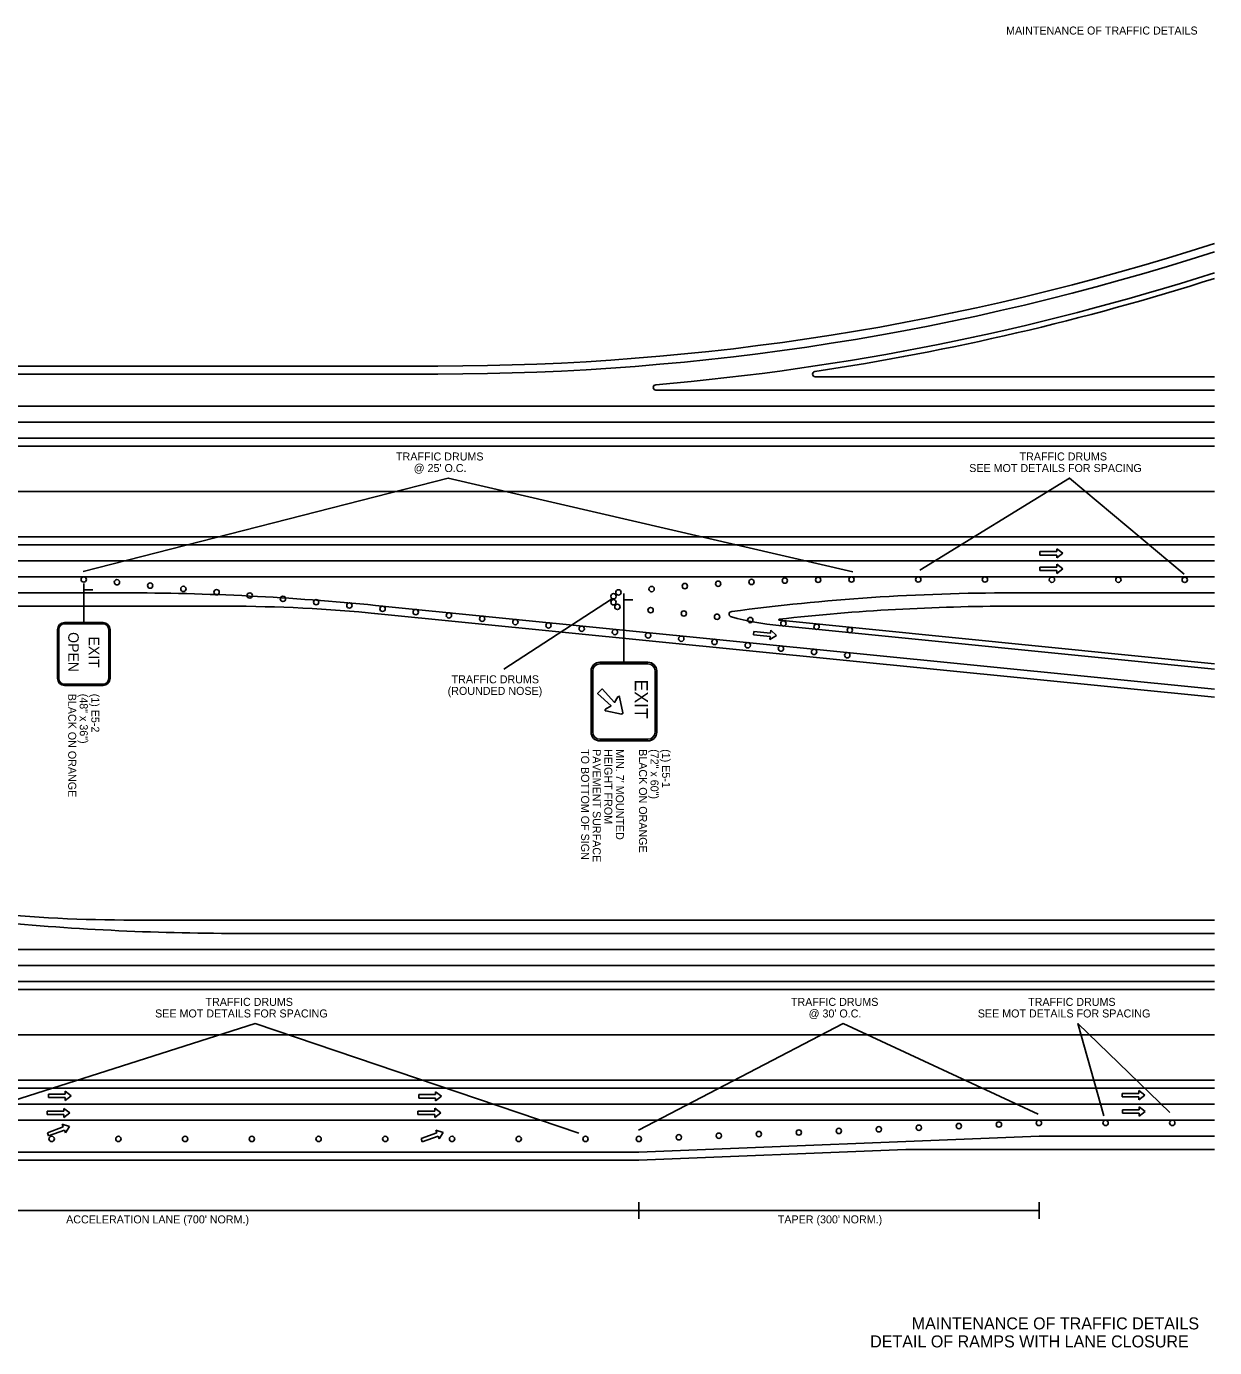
# Model space of a CAD drawing. Extents: x 1373848 to 1374003, y 380642 to 381248.
# Drawn here: x 1373914.2 to 1374003.2, y 380810.3 to 380909.4 of the extents above; entities that cross this region are included whole.
import ezdxf

# ---------------------------------------------------------------- set-up
doc = ezdxf.new("R2010")
doc.units = 0
for name, color, linetype in [('Default', 7, 'Continuous'), ('G-ANNO-TEXT', 7, 'Continuous'), ('R_Horz Alg', 7, 'Continuous'), ('R_MOT', 7, 'Continuous')]:
    doc.layers.add(name, color=color, linetype=linetype)

# ---------------------------------------------------------------- blocks, each defined once
blk = doc.blocks.new('SARROW')
at = {"layer": 'Default'}
for p, q in [((15.6, 3.2), (-13.8, 3.2)), ((-13.8, 3.2), (-13.8, -2.8)), ((15.6, 8.2), (15.6, 3.2)), ((15.6, 8.2), (26, 0.2)), ((26, 0.2), (15.6, -7.8)), ((15.6, -2.8), (-13.8, -2.8)), ((15.6, -2.8), (15.6, -7.8))]:
    blk.add_line(p, q, dxfattribs=at)

msp = doc.modelspace()

# ---------------------------------------------------------------- linework, layer by layer
at = {"layer": 'Default'}
for p, q in [((1373945.02, 380883.909), (1373891.355, 380883.909)), ((1373945.02, 380883.309), (1373891.355, 380883.309)), ((1373973.291, 380883.109), (1374003.214, 380883.109)), ((1373961.355, 380882.109), (1374003.214, 380882.109)), ((1373848.214, 380880.909), (1374003.214, 380880.909)), ((1373848.214, 380879.709), (1374003.214, 380879.709)), ((1373848.214, 380878.509), (1374003.214, 380878.509)), ((1373848.214, 380877.909), (1374003.214, 380877.909)), ((1373848.214, 380874.509), (1374003.214, 380874.509)), ((1373848.214, 380871.109), (1374003.214, 380871.109)), ((1373848.214, 380870.509), (1374003.214, 380870.509)), ((1373848.214, 380869.309), (1374003.214, 380869.309)), ((1373848.214, 380868.109), (1374003.214, 380868.109)), ((1373848.214, 380866.909), (1373921.443, 380866.909)), ((1373988.03, 380866.909), (1374003.214, 380866.909)), ((1373848.214, 380865.909), (1373929.25, 380865.909)), ((1374003.214, 380859.079), (1373940.282, 380865.37)), ((1374003.214, 380859.682), (1373940.342, 380865.967)), ((1374003.214, 380865.909), (1373988.03, 380865.909)), ((1374003.214, 380861.19), (1373970.562, 380864.453)), ((1374003.214, 380861.592), (1373970.602, 380864.851)), ((1374003.214, 380842.381), (1373922.177, 380842.381)), ((1374003.214, 380841.381), (1373929.984, 380841.381)), ((1374003.214, 380840.181), (1373848.214, 380840.181)), ((1374003.214, 380838.981), (1373848.214, 380838.981)), ((1374003.214, 380837.781), (1373848.214, 380837.781)), ((1374003.214, 380837.181), (1373848.214, 380837.181)), ((1374003.214, 380833.781), (1373848.214, 380833.781)), ((1374003.214, 380830.381), (1373848.214, 380830.381)), ((1374003.214, 380829.781), (1373848.214, 380829.781)), ((1374003.214, 380828.581), (1373848.214, 380828.581)), ((1374003.214, 380827.381), (1373848.214, 380827.381)), ((1373960.072, 380824.981), (1373990.072, 380826.181)), ((1373990.072, 380826.181), (1374003.214, 380826.181)), ((1373906.407, 380824.981), (1373960.072, 380824.981)), ((1373960.072, 380824.381), (1373980.072, 380825.181)), ((1373980.072, 380825.181), (1374003.214, 380825.181)), ((1373906.407, 380824.381), (1373960.072, 380824.381)), ((1373960.072, 380820.608), (1373890.072, 380820.608)), ((1373960.072, 380821.233), (1373960.072, 380819.983)), ((1373960.072, 380820.608), (1373990.072, 380820.608)), ((1373990.072, 380821.233), (1373990.072, 380819.983))]:
    msp.add_line(p, q, dxfattribs=at)
for centre, radius, start, end in [((1373945.02, 381072.559), 188.65, 270, 287.96736), ((1373945.02, 381072.559), 189.25, 270, 287.90846), ((1373945.02, 381072.559), 190.75, 274.90749, 287.76292), ((1373945.02, 381072.559), 191.15, 278.49632, 287.72452), ((1373973.291, 380883.309), 0.2, 98.49632, 270), ((1373961.355, 380882.309), 0.2, 94.90749, 270), ((1373921.443, 380676.909), 190, 84.29167, 90), ((1373988.03, 380708.709), 158.2, 90, 97.62815), ((1373929.25, 380752.831), 113.078, 84.29167, 90), ((1373967.03, 380865.309), 0.2, 90, 264.29167), ((1373988.03, 380708.709), 157.2, 90, 96.36869), ((1373972.726, 380886.096), 21.75, 254.76438, 264.29167), ((1373970.604, 380864.896), 0.0444, 104.39417, 268.34322), ((1373922.177, 380955.458), 113.078, 264.29167, 270), ((1373929.984, 381031.381), 190, 264.29167, 270)]:
    msp.add_arc(centre, radius, start, end, dxfattribs=at)
at = {"layer": 'R_Horz Alg'}
for p, q in [((1373916.51, 380864.163), (1373916.51, 380860.488)), ((1373916.608, 380864.163), (1373916.608, 380860.488)), ((1373919.922, 380864.688), (1373917.034, 380864.688)), ((1373919.922, 380864.589), (1373917.034, 380864.589)), ((1373920.348, 380860.488), (1373920.348, 380864.163)), ((1373920.447, 380860.488), (1373920.447, 380864.163)), ((1373960.754, 380861.713), (1373957.145, 380861.713)), ((1373960.754, 380861.59), (1373957.145, 380861.59)), ((1373956.489, 380861.057), (1373956.489, 380856.464)), ((1373956.612, 380861.057), (1373956.612, 380856.464)), ((1373961.287, 380856.464), (1373961.287, 380861.057)), ((1373961.41, 380856.464), (1373961.41, 380861.057)), ((1373917.034, 380860.062), (1373919.922, 380860.062)), ((1373917.034, 380859.963), (1373919.922, 380859.963)), ((1373958.633, 380859.102), (1373958.864, 380857.909)), ((1373958.784, 380857.829), (1373957.591, 380858.057)), ((1373957.145, 380855.931), (1373960.754, 380855.931)), ((1373957.145, 380855.808), (1373960.754, 380855.808))]:
    msp.add_line(p, q, dxfattribs=at)
msp.add_lwpolyline([(1373957.571, 380858.185), (1373957.991, 380858.442), (1373956.981, 380859.371), (1373957.319, 380859.71), (1373958.248, 380858.698), (1373958.507, 380859.122)], dxfattribs=at)
for centre in [(1373918.478, 380867.909), (1373920.966, 380867.704), (1373923.453, 380867.455), (1373925.941, 380867.206), (1373928.428, 380866.958), (1373958.544, 380866.942), (1373961.03, 380867.198), (1373963.521, 380867.415), (1373966.015, 380867.593), (1373968.511, 380867.731), (1373971.009, 380867.83), (1373973.508, 380867.889), (1373976.008, 380867.909), (1373981.008, 380867.909), (1373986.008, 380867.909), (1373991.03, 380867.897), (1373996.005, 380867.891), (1374000.98, 380867.886), (1373930.916, 380866.709), (1373933.404, 380866.46), (1373935.891, 380866.212), (1373938.379, 380865.963), (1373958.173, 380866.205), (1373958.174, 380866.65), (1373940.866, 380865.714), (1373943.354, 380865.466), (1373945.842, 380865.217), (1373948.329, 380864.968), (1373958.468, 380865.862), (1373960.956, 380865.614), (1373963.444, 380865.365), (1373965.931, 380865.116), (1373950.817, 380864.72), (1373953.304, 380864.471), (1373955.792, 380864.222), (1373958.28, 380863.974), (1373968.419, 380864.868), (1373970.906, 380864.619), (1373973.394, 380864.37), (1373975.882, 380864.122), (1373960.767, 380863.725), (1373963.255, 380863.476), (1373965.742, 380863.228), (1373968.23, 380862.979), (1373970.718, 380862.73), (1373973.205, 380862.482), (1373975.693, 380862.233), (1373969.065, 380826.34), (1373972.063, 380826.46), (1373975.06, 380826.58), (1373978.058, 380826.7), (1373981.055, 380826.82), (1373984.053, 380826.94), (1373987.051, 380827.06), (1373990.048, 380827.18), (1373995.048, 380827.18), (1374000.048, 380827.18), (1373916.072, 380825.981), (1373921.072, 380825.981), (1373926.072, 380825.981), (1373931.072, 380825.981), (1373936.072, 380825.981), (1373941.072, 380825.981), (1373946.072, 380825.981), (1373951.072, 380825.981), (1373956.072, 380825.981), (1373960.072, 380825.981), (1373963.07, 380826.1), (1373966.067, 380826.22)]:
    msp.add_circle(centre, 0.2, dxfattribs=at)
for centre, radius, start, end in [((1373917.034, 380864.163), 0.525, 90, 180), ((1373917.034, 380864.163), 0.427, 90, 180), ((1373919.922, 380864.163), 0.525, 0, 90), ((1373919.922, 380864.163), 0.427, 0, 90), ((1373957.145, 380861.057), 0.656, 90, 180), ((1373957.145, 380861.057), 0.533, 90, 180), ((1373960.754, 380861.057), 0.656, 0, 90), ((1373960.754, 380861.057), 0.533, 0, 90), ((1373917.034, 380860.488), 0.525, 180, 270), ((1373917.034, 380860.488), 0.427, 180, 270), ((1373919.922, 380860.488), 0.525, 270, 0), ((1373919.922, 380860.488), 0.427, 270, 0), ((1373958.566, 380859.089), 0.0676, 11.60513, 150.8846), ((1373957.605, 380858.124), 0.0689, 118.94645, 258.30458), ((1373958.798, 380857.896), 0.0676, 258.14413, 11.77249), ((1373957.145, 380856.464), 0.656, 180, 270), ((1373957.145, 380856.464), 0.533, 180, 270), ((1373960.754, 380856.464), 0.656, 270, 0), ((1373960.754, 380856.464), 0.533, 270, 0)]:
    msp.add_arc(centre, radius, start, end, dxfattribs=at)
at = {"layer": 'R_MOT'}
for p, q in [((1373918.478, 380867.602), (1373918.478, 380866.645)), ((1373918.478, 380867.126), (1373919.145, 380867.126)), ((1373918.478, 380864.589), (1373918.478, 380866.645)), ((1373958.949, 380866.854), (1373958.949, 380865.897)), ((1373958.949, 380866.378), (1373959.617, 380866.378)), ((1373958.949, 380861.713), (1373958.949, 380865.897))]:
    msp.add_line(p, q, dxfattribs=at)
for points in [[(1373918.435, 380868.522), (1373945.792, 380875.508), (1373976.107, 380868.491)], [(1373981.139, 380868.601), (1373992.336, 380875.508), (1374000.941, 380868.299)], [(1373949.952, 380861.186), (1373958.033, 380866.427)], [(1373906.081, 380826.579), (1373931.333, 380834.626), (1373955.564, 380826.402)], [(1373960.04, 380826.639), (1373975.384, 380834.626), (1373990.006, 380827.844)], [(1373994.907, 380827.699), (1373992.978, 380834.626), (1373999.854, 380827.956)]]:
    msp.add_lwpolyline(points, dxfattribs=at)

# ---------------------------------------------------------------- block references
for p, xscale, yscale, rotation in [((1373990.717, 380869.867), 0.0428571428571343, 0.0428571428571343, -8.252131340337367e-12), ((1373990.717, 380868.699), 0.0428571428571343, 0.0428571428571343, -8.252131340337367e-12), ((1373969.266, 380863.823), 0.0428571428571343, 0.0428571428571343, -5.708333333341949), ((1373916.414, 380829.203), 0.0428571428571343, 0.0428571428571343, -8.252131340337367e-12), ((1373944.178, 380829.165), 0.0428571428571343, 0.0428571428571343, -8.252131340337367e-12), ((1373996.87, 380829.247), 0.0428571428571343, 0.0428571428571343, -8.252131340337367e-12), ((1373916.325, 380827.919), 0.0428571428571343, 0.0428571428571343, -8.252131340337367e-12), ((1373944.11, 380827.924), 0.0428571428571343, 0.0428571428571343, -8.252131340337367e-12), ((1373996.904, 380828.025), 0.0428571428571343, 0.0428571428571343, -8.252131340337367e-12), ((1373916.361, 380826.515), 0.042857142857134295, 0.04285714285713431, 19.999999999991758), ((1373944.359, 380826.079), 0.042857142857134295, 0.04285714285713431, 19.999999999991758)]:
    msp.add_blockref('SARROW', p, dxfattribs=dict(at, xscale=xscale, yscale=yscale, rotation=rotation))

# ---------------------------------------------------------------- texts
at = {"layer": 'G-ANNO-TEXT'}
for s, height, p in [('MAINTENANCE OF TRAFFIC DETAILS', 0.6, (1373987.593, 380908.759)), ('MAINTENANCE OF TRAFFIC DETAILS', 0.9, (1373980.522, 380811.701)), ('DETAIL OF RAMPS WITH LANE CLOSURE', 0.9, (1373977.404, 380810.351))]:
    msp.add_text(s, height=height, dxfattribs=at).set_placement(p)
at = {"layer": 'R_Horz Alg'}
for s, height, p in [('OPEN', 0.7874, (1373917.313, 380863.966)), ('EXIT', 0.7874, (1373918.855, 380863.638)), ('EXIT', 0.9842, (1373959.77, 380860.402))]:
    msp.add_text(s, height=height, rotation=270, dxfattribs=at).set_placement(p)
at = {"layer": 'R_MOT'}
for s, p in [('TRAFFIC DRUMS ', (1373941.878, 380876.832)), ('TRAFFIC DRUMS', (1373988.601, 380876.832)), ("@ 25' O.C.", (1373943.201, 380875.965)), ('SEE MOT DETAILS FOR SPACING', (1373984.829, 380875.965)), ('TRAFFIC DRUMS ', (1373946.039, 380860.129)), ('(ROUNDED NOSE)', (1373945.746, 380859.262)), ('TRAFFIC DRUMS', (1373927.599, 380835.95)), ('TRAFFIC DRUMS ', (1373971.47, 380835.95)), ('TRAFFIC DRUMS', (1373989.243, 380835.95)), ('SEE MOT DETAILS FOR SPACING', (1373923.826, 380835.083)), ("@ 30' O.C.", (1373972.795, 380835.083)), ('SEE MOT DETAILS FOR SPACING', (1373985.471, 380835.083))]:
    msp.add_text(s, height=0.6, dxfattribs=at).set_placement(p)
for s, rotation, p in [('BLACK ON ORANGE', 270, (1373917.311, 380859.348)), ('(48" x 36")', 270, (1373918.178, 380859.348)), ('(1) E5-2', 270, (1373919.045, 380859.348)), ('TO BOTTOM OF SIGN', 270, (1373955.749, 380855.193)), ('PAVEMENT SURFACE', 270, (1373956.616, 380855.193)), ('HEIGHT FROM', 270, (1373957.483, 380855.193)), ("MIN. 7' MOUNTED", 270, (1373958.349, 380855.193)), ('BLACK ON ORANGE', 270, (1373960.083, 380855.193)), ('(72" x 60")', 270, (1373960.949, 380855.193)), ('(1) E5-1', 270, (1373961.816, 380855.193)), ("ACCELERATION LANE (700' NORM.)", 0, (1373917.156, 380819.647)), ("TAPER (300' NORM.)", 0, (1373970.486, 380819.647))]:
    msp.add_text(s, height=0.6, rotation=rotation, dxfattribs=at).set_placement(p)

doc.saveas('drawing.dxf')
